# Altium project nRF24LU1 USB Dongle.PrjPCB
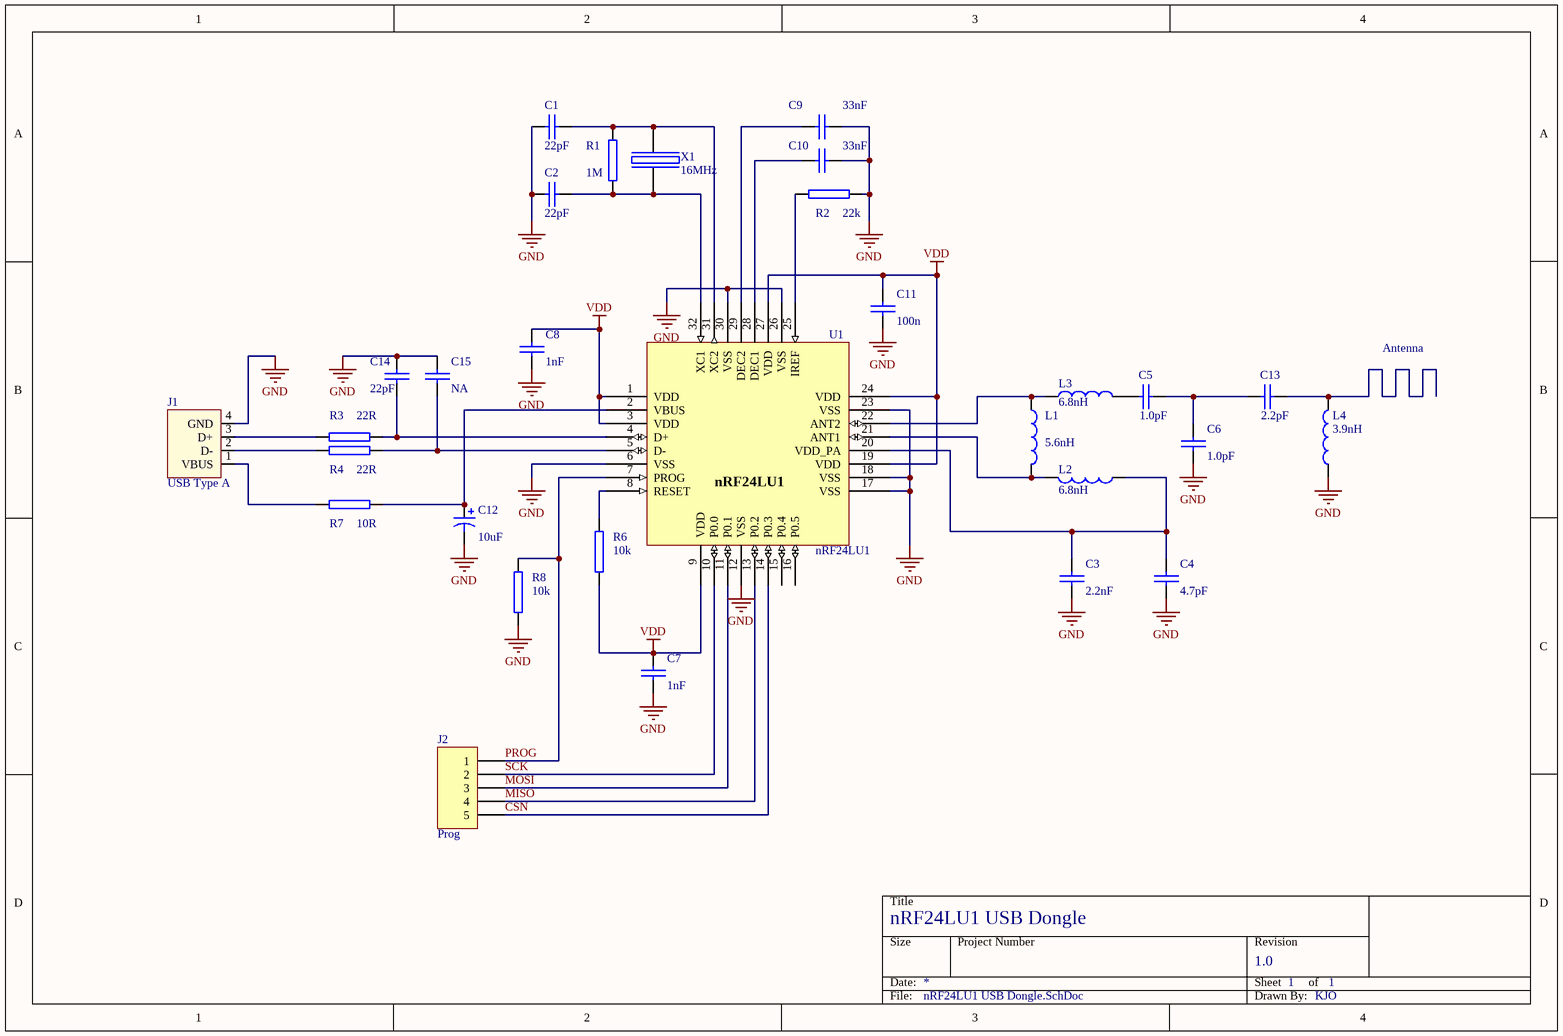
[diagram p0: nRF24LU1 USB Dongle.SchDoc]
1 sheet, 30 parts. Net scope: global (net labels, ports and power ports of the same name join across sheets).
Board file: nRF24LU1 USB Dongle.PcbDoc

## Sheet nRF24LU1 USB Dongle.SchDoc: nRF24LU1 USB Dongle
size A4; Revision: 1.0; SheetNumber: 1; SheetTotal: 1; DrawnBy: KJO

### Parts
C1  value 22pF  [0402s]  (hidden comment: NP0 +/-2%)
C2  value 22pF  [0402s]  (hidden comment: NP0 +/-2%)
C3  value 2.2nF  [0402s]  (hidden comment: X7R +/-10%)
C4  value 4.7pF  [0402s]  (hidden comment: NP0 +/-2%)
C5  value 1.0pF  [0402s]  (hidden comment: NP0 +/-2%)
C6  value 1.0pF  [0402s]  (hidden comment: NP0 +/-2%)
C7  value 1nF  [0402s]  (hidden comment: X7R +/-10%)
C8  value 1nF  [0402s]  (hidden comment: X7R +/-10%)
C9  value 33nF  [0402s]  (hidden comment: X7R, +/-10%)
C10  value 33nF  [0402s]  (hidden comment: X7R, +/-10%)
C11  value 100n  [0402s]  (hidden comment: X7R +/-10%)
C12  value 10uF  [0603s]  (hidden comment: X5R +/-10%, 6.3v)
C13  value 2.2pF  [0402s]  (hidden comment: NP0 +/-2%)
C14  value 22pF  [0402s]  (hidden comment: NP0 +/-2%)
C15  value NA  [0402s]
J1  USB Type A  [ACIN USD SMD]
J2  Digikey 455-1791-1-ND  [SH-5]  (value not drawn)
L1  value 5.6nH  [0402s]  (hidden comment: Chip Inductor +/-5%)
L2  value 6.8nH  [0402s]  (hidden comment: Chip Inductor +/-5%)
L3  value 6.8nH  [0402s]  (hidden comment: Chip Inductor +/-5%)
L4  value 3.9nH  [0402s]  (hidden comment: Chip Inductor +/-5%)
R1  value 1M  [0402s]  (hidden comment: 5%)
R2  value 22k  [0402s]  (hidden comment: 1%)
R3  value 22R  [0402s]  (hidden comment: 5%)
R4  value 22R  [0402s]  (hidden comment: 5%)
R6  value 10k  [0402s]  (hidden comment: 5%)
R7  value 10R  [0402s]  (hidden comment: 5%)
R8  value 10k  [0402s]  (hidden comment: 5%)
U1  nRF24LU1  [QFN32L/5x5]
X1  value 16MHz  [BT-XTAL 2520]  (hidden comment: FA-20H 16MHz, CL=12pF)

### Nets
GND: C1.2 C2.1 C3.1 C4.1 C6.2 C7.2 C8.2 C9.1 C10.1 C11.2 C12.2 C14.2 C15.2 J1.4(GND) L4.1 R2.2 R8.2 U1.6(VSS) U1.12(VSS) U1.17(VSS) U1.18(VSS) U1.23(VSS) U1.26(VSS) U1.30(VSS) X1.2(GND) X1.4(GND)
VDD: C7.1 C8.1 C11.1 R6.2 U1.1(VDD) U1.3(VDD) U1.9(VDD) U1.19(VDD) U1.24(VDD) U1.27(VDD)
CSN: J2.5 U1.14(P0.3)
MISO: J2.4 U1.13(P0.2)
MOSI: J2.3 U1.11(P0.1)
PROG: J2.1 R8.1 U1.7(PROG)
SCK: J2.2 U1.10(P0.0)
NetC1_1: C1.1 R1.1 U1.31(XC2) X1.1(inp)
NetC2_2: C2.2 R1.2 U1.32(XC1) X1.3(out)
NetC3_2: C3.2 C4.2 L2.1 U1.20(VDD_PA)
NetC5_1: C5.1 C6.1 C13.2
NetC5_2: C5.2 L3.2
NetC9_2: C9.2 U1.29(DEC2)
NetC10_2: C10.2 U1.28(DEC1)
NetC12_1: C12.1 R7.1 U1.2(VBUS)
NetC13_1: C13.1 L4.2
NetC14_1: C14.1 R3.1 U1.4(D+)
NetC15_1: C15.1 R4.1 U1.5(D-)
NetJ1_1: J1.1(VBUS) R7.2
NetJ1_2: J1.2(D-) R4.2
NetJ1_3: J1.3(D+) R3.2
NetL1_1: L1.1 L3.1 U1.22(ANT2)
NetL1_2: L1.2 L2.2 U1.21(ANT1)
NetR2_1: R2.1 U1.25(IREF)
NetR6_1: R6.1 U1.8(RESET)

Not connected (* = marked no-connect by the designer): U1 15(P0.4) 16(P0.5)

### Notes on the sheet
- Antenna
- (near J2) Prog

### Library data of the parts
C1-C11 C13-C15 = CAP: Part Field 1: 0402
C12 = Cap Pol3: Polarized Capacitor (Surface Mount)
J1 = USB_PCB: Value: Molex 48037-1000
J2 = Header 5: Header, 5-Pin; Value: JST BM05B-SRSS-TB
L1-L4 = INDUCTOR1: Part Field 1: 0402
R1-R4 R6-R8 = RES2: Part Field 1: 0402
U1 = nRF24LU1: 2.4GHz Transceiver with USB
X1 = BT-XTAL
